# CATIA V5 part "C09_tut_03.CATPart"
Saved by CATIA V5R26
Part number: Part1
Bounding box of the stored display mesh (mm): x 0 to 224, y -87.737 to 88.937, z 0 to 67.047
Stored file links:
  D:\_Deepak\CATIA\CATIA V5 2015 Parts Files\Tutorial Files\Tutorials\c09_catia_v5_6r2015_tut\C09_tut_03.CATPart
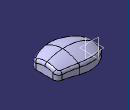
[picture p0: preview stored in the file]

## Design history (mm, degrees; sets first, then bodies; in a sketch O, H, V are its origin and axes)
Body1 (main body)
  Sketch1 on xy-plane, origin (0, 0, 0), H (1, 0, 0), V (0, 1, 0)
    arc A1 centre (95, -36.2404) radius 125 from (0, 45) to (139.6657, 80.5071) cw
    point P1 (95, -36.2404)
    point P2 (0, 45)
    arc A2 centre (289.027, 470.911) radius 418 from (139.6657, 80.5071) to (224, 58) ccw
    point P5 (224, 58)
    radius A1 = 125
    distance P2 H = 45
    distance P2 P5 H = 224
    radius A2 = 418
    distance P5 H = 58
    distance P1 V = 95
    coincidence: P2 V
    tangency: A2 A1
  Sketch2 on xy-plane, origin (0, 0, 0), H (1, 0, 0), V (0, 1, 0)
    axis line L1 (0, -58) -> (224, -58)
    point P1 (0, -58)
    point P2 (224, -58)
    arc A1 centre (112, 154.264) radius 240 from (0, -58) to (224, -58) ccw
    length L1 = 224
    radius A1 = 240
    distance H L1 = 58
    coincidence: P1 V
    horizontal: L1 H
  Sketch3 on zx-plane, origin (0, 0, 0), H (-1, 0, 0), V (0, 0, 1)
    arc A1 centre (-126.7082, -167.9142) radius 235 from (0, 30) to (-224, 46) ccw
    point P2 (0, 30)
    point P3 (-224, 46)
    axis line L1 (-224, 46) -> (-224, 0)
    point P4 (-224, 0)
    radius A1 = 235
    distance P2 H = 30
    length L1 = 46
    distance P2 P3 H = 224
    coincidence: P2 V, P4 H
    vertical: L1 V
  Sketch4 on yz-plane, origin (0, 0, 0), H (0, 1, 0), V (0, 0, 1)
    point P1 (45, 0)
    line L1 (45, 0) -> (45, 18.2879)
    point P3 (-58, 0)
    line L2 (-58, 0) -> (-58, 18.9081)
    arc A1 centre (-7.1526, -89.7866) radius 120 from (-58, 18.9081) to (45, 18.2879) cw
    point P6 (0, 30)
    line L3 (45, 0) -> (-58, 0)
    reference projected point E1 (-58, 0) from Sketch2.P1
    reference projected point E2 (45, 0) from Sketch1.P2
    reference projected point E3 (0, 30) from Sketch3.P2
    radius A1 = 120
    coincidence: P1 H, P3 H, A1 P6, P6 V, P3 E1, P1 E2, P6 E3
    vertical: L1 V, L2 V
    horizontal: L3 H
  Plane1: type 3Points, Element1 Sketch2.P2, Element2 Sketch3.P3, Element3 Sketch1.P5
  Sketch5 on Plane1, origin (224, 0, 0), H (0, -1, 0), V (0, 0, 1)
    point P1 (-58, 0)
    line L1 (-58, 0) -> (58, 0)
    point P2 (58, 0)
    line L2 (58, 0) -> (58, 29.9794)
    arc A1 centre (0, -67) radius 113 from (58, 29.9794) to (-58, 29.9794) ccw
    point P5 (0, 46)
    line L3 (-58, 29.9794) -> (-58, 0)
    reference projected point E1 (-58, 0) from Sketch1.P5
    reference projected point E2 (58, 0) from Sketch2.P2
    reference projected point E3 (0, 46) from Sketch3.P3
    axis line L4 (58, 29.9794) -> (-58, 29.9794)
    radius A1 = 113
    coincidence: P1 H, A1 P5, P5 V, P1 E1, P2 E2, P5 E3
    horizontal: L1 H, L4 H
    vertical: L2 V, L3 V
  Loft1: solid, Sections (Sketch4; Sketch5), Guides (Sketch1; Sketch3; Sketch2)
  Fillet1: radius 25, on edge [face of Loft1 | face of Loft1] (x2)
  Fillet2: radius 15, on edge [face of Loft1 | face of Loft1]
  Shell1: ExtOffset 0, Face (face of Loft1; face of Loft1), IntOffset 3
